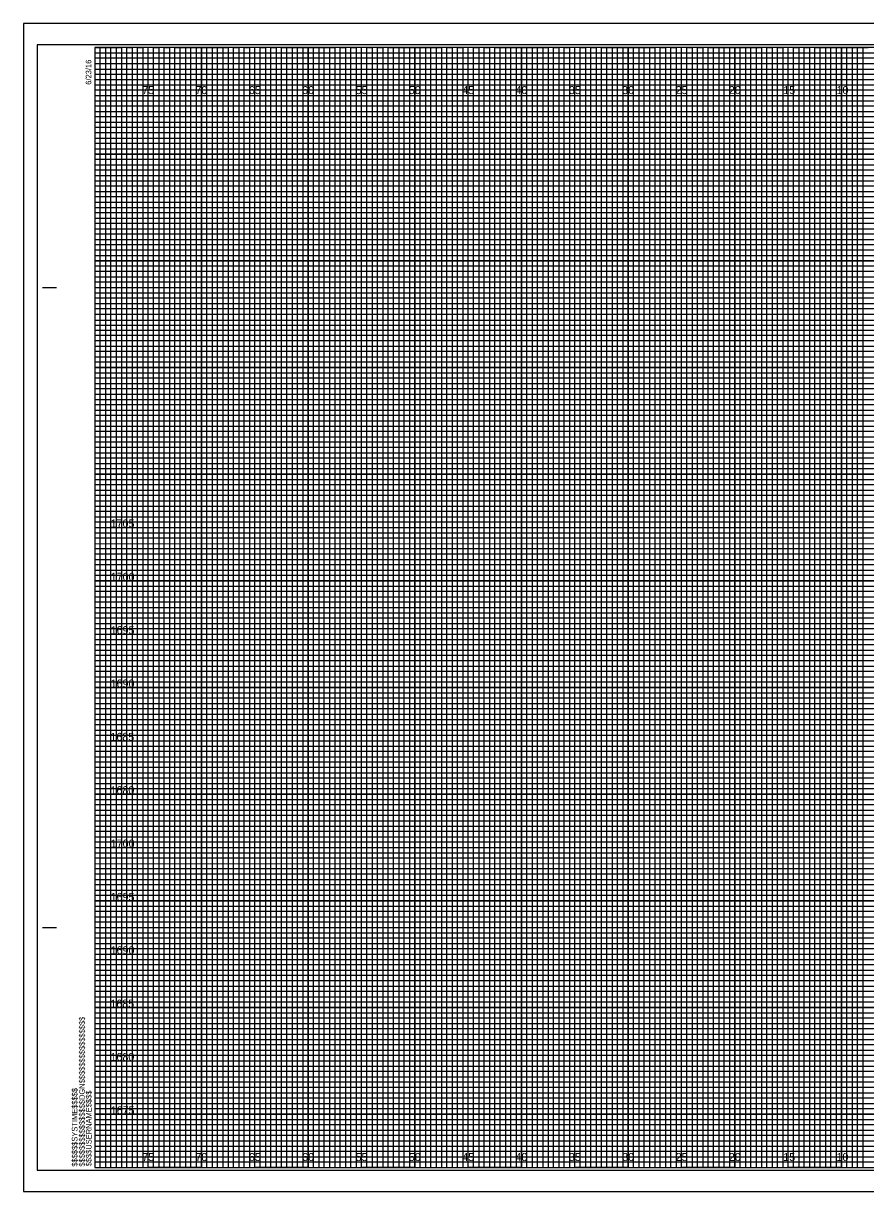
# Model space of a CAD drawing. Extents: x -7 to 162, y -2 to 217.
# Drawn here: x -6.7 to 72.2, y 107.7 to 217.2 of the extents above; entities that cross this region are included whole.
import ezdxf

# ---------------------------------------------------------------- set-up
doc = ezdxf.new("R2010")
doc.units = 0
for name, color, linetype in [('Raster_Level_0', 7, 'Continuous'), ('Scratch_Level_3', 7, 'Continuous'), ('Sheet Cross Section CELL', 7, 'Continuous'), ('Sheet Cross Section Grid Major CELL', 7, 'Continuous'), ('Sheet Cross Section Grid Middle CELL', 7, 'Continuous'), ('Sheet Cross Section Grid Minor 1 CELL', 7, 'Continuous'), ('Sheet Cross Section Grid Minor 2 CELL', 7, 'Continuous'), ('Sheet Cutting Line CELL', 7, 'Continuous'), ('Sheet DOT Grid CELL', 7, 'Continuous'), ('Sheet Plot Border Inside CELL', 7, 'Continuous'), ('Sheet Plot Border Outside CELL', 7, 'Continuous')]:
    doc.layers.add(name, color=color, linetype=linetype)

msp = doc.modelspace()

# ---------------------------------------------------------------- linework, layer by layer
at = {"layer": 'Sheet Cross Section CELL'}
for p, q in [((-4.9, 192.5), (-3.65, 192.5)), ((-4.85, 192.5), (-3.6, 192.5)), ((-4.9, 132.5), (-3.65, 132.5)), ((-4.85, 132.5), (-3.6, 132.5)), ((0, 110), (0, 110)), ((0, 110), (0, 110)), ((0, 110), (0, 110)), ((0, 110), (0, 110)), ((0, 110), (0, 110)), ((0, 110), (0, 110)), ((0, 110), (0, 110))]:
    msp.add_line(p, q, dxfattribs=at)
msp.add_lwpolyline([(160, 215), (0, 215), (0, 110), (160, 110)], close=True, dxfattribs=at)
at = {"layer": 'Sheet Cross Section Grid Major CELL'}
for p, q in [((5, 215), (0, 215)), ((5, 110), (5, 215)), ((15, 215), (10, 215)), ((10, 215), (10, 110)), ((15, 110), (15, 215)), ((25, 215), (20, 215)), ((20, 215), (20, 110)), ((25, 110), (25, 215)), ((35, 215), (30, 215)), ((30, 215), (30, 110)), ((35, 110), (35, 215)), ((45, 215), (40, 215)), ((40, 215), (40, 110)), ((45, 110), (45, 215)), ((55, 215), (50, 215)), ((50, 215), (50, 110)), ((55, 110), (55, 215)), ((65, 215), (60, 215)), ((60, 215), (60, 110)), ((65, 110), (65, 215)), ((75, 215), (70, 215)), ((70, 215), (70, 110)), ((10, 110), (5, 110)), ((20, 110), (15, 110)), ((30, 110), (25, 110)), ((40, 110), (35, 110)), ((50, 110), (45, 110)), ((60, 110), (55, 110)), ((70, 110), (65, 110))]:
    msp.add_line(p, q, dxfattribs=at)
for points in [[(0, 210), (160, 210), (160, 205), (0, 205)], [(0, 200), (160, 200), (160, 195), (0, 195)], [(0, 190), (160, 190), (160, 185), (0, 185)], [(0, 180), (160, 180), (160, 175), (0, 175)], [(0, 170), (160, 170), (160, 165), (0, 165)], [(0, 160), (160, 160), (160, 155), (0, 155)], [(0, 150), (160, 150), (160, 145), (0, 145)], [(0, 140), (160, 140), (160, 135), (0, 135)], [(0, 130), (160, 130), (160, 125), (0, 125)], [(0, 120), (160, 120), (160, 115), (0, 115)]]:
    msp.add_lwpolyline(points, dxfattribs=at)
at = {"layer": 'Sheet Cross Section Grid Middle CELL'}
for points in [[(0, 215), (2.5, 215), (2.5, 110), (7.5, 110), (7.5, 215), (12.5, 215), (12.5, 110), (17.5, 110), (17.5, 215), (22.5, 215), (22.5, 110), (27.5, 110), (27.5, 215), (32.5, 215), (32.5, 110), (37.5, 110), (37.5, 215), (42.5, 215), (42.5, 110), (47.5, 110), (47.5, 215), (52.5, 215), (52.5, 110), (57.5, 110), (57.5, 215), (62.5, 215), (62.5, 110), (67.5, 110), (67.5, 215), (72.5, 215)], [(0, 212.5), (137.5, 212.5)], [(0, 202.5), (160, 202.5), (160, 207.5), (0, 207.5)], [(0, 192.5), (160, 192.5), (160, 197.5), (0, 197.5)], [(0, 182.5), (160, 182.5), (160, 187.5), (0, 187.5)], [(0, 172.5), (160, 172.5), (160, 177.5), (0, 177.5)], [(0, 162.5), (160, 162.5), (160, 167.5), (0, 167.5)], [(0, 152.5), (160, 152.5), (160, 157.5), (0, 157.5)], [(0, 142.5), (160, 142.5), (160, 147.5), (0, 147.5)], [(0, 132.5), (160, 132.5), (160, 137.5), (0, 137.5)], [(0, 122.5), (160, 122.5), (160, 127.5), (0, 127.5)], [(0, 112.5), (160, 112.5), (160, 117.5), (0, 117.5)]]:
    msp.add_lwpolyline(points, dxfattribs=at)
at = {"layer": 'Sheet Cross Section Grid Minor 1 CELL'}
for p, q in [((0, 214.5), (130, 214.5)), ((130, 213.99), (0, 213.99)), ((0, 213.99), (0, 213.5)), ((0, 213.5), (130, 213.5)), ((130, 212.94), (0, 212.94)), ((0, 212.94), (0, 212)), ((0, 212), (160, 212))]:
    msp.add_line(p, q, dxfattribs=at)
for points in [[(0, 211.5), (135, 211.5), (160, 211.5), (160, 211), (0, 211)], [(0, 210.5), (160, 210.5), (160, 209.5), (0, 209.5)], [(0, 209), (160, 209), (160, 208.5), (0, 208.49)], [(0, 208), (160, 208), (160, 207), (0, 207)], [(0, 206.5), (160, 206.5), (160, 206), (0, 206)], [(0, 205.5), (160, 205.5), (160, 204.5), (0, 204.5)], [(0, 204), (160, 204), (160, 203.5), (0, 203.5)], [(0, 203), (160, 203), (160, 202), (0, 202)], [(0, 201.5), (160, 201.5), (160, 201), (0, 201)], [(0, 200.5), (160, 200.5), (160, 199.5), (0, 199.5)], [(0, 199), (160, 199), (160, 198.5), (0, 198.5)], [(0, 198), (160, 198), (160, 196.97), (160, 196.5), (160, 196), (0, 196)], [(0, 197), (160, 197), (160, 196.5), (0, 196.5)], [(0, 195.5), (160, 195.5), (160, 194.5), (0, 194.52)], [(0, 194.52), (160, 194.5), (160, 194), (0, 194)], [(0, 193.5), (160, 193.5), (160, 193), (0, 193)], [(0, 192), (160, 192), (160, 191.5), (0, 191.5)], [(0, 191), (160, 191), (160, 190.5), (0, 190.5)], [(-0.04, 189.44), (160, 189.44), (160, 188.94), (-0.04, 188.94)], [(0, 188.5), (160, 188.5), (160, 188), (0, 188)], [(0, 187), (160, 187), (160, 186.5), (0, 186.5)], [(0, 186), (160, 186), (160, 185.5), (0, 185.5)], [(0, 184.5), (160, 184.5), (160, 184), (0, 184)], [(0, 183.5), (160, 183.5), (160, 183), (0, 183)], [(0, 182), (160, 182), (160, 181.5), (0, 181.5)], [(0, 181), (160, 181), (160, 180.5), (0, 180.5)], [(0, 179.5), (160, 179.5), (160, 178.99), (0, 179)], [(0, 178.5), (160, 178.5), (160, 178), (0, 178)], [(0, 177), (160, 177), (160, 176.5), (0, 176.5)], [(0, 176), (160, 176), (160, 175.5), (0, 175.5)], [(0, 174.5), (160, 174.5), (160, 174), (0, 174)], [(0, 173.5), (160, 173.5), (160, 173), (0, 173)], [(0, 172), (160, 172), (160, 171.5), (0, 171.5)], [(0, 171), (160, 171), (160, 170.5), (0, 170.5)], [(0, 169.5), (160, 169.5), (160, 169), (0, 169)], [(0, 168.5), (160.03, 168.46), (160, 168), (0, 168)], [(0, 167), (160, 167), (160, 166.5), (0, 166.5)], [(0, 166), (160, 166), (160, 165.5), (0, 165.5)], [(0, 164.5), (160, 164.5), (160, 164), (0, 164)], [(0, 163.5), (160, 163.5), (160, 163), (0, 163)], [(0, 162), (160, 162), (160, 161.5), (0, 161.5)], [(0, 161), (160, 161), (160, 160.5), (0, 160.5)], [(0, 159.5), (160, 159.5), (160, 159), (0, 159)], [(0, 158.5), (160, 158.5), (160, 158), (0, 158)], [(0, 157), (160, 157), (160, 156.5), (0, 156.5)], [(0, 156), (160, 156), (160, 155.5), (0, 155.5)], [(0, 154.5), (160, 154.5), (160, 154), (0, 154)], [(0, 153.5), (160, 153.5), (160, 153), (0, 153)], [(0, 152), (160, 152), (160, 151.5), (0, 151.5)], [(0, 151), (160, 151), (160, 150.5), (0, 150.5)], [(0, 149.5), (160, 149.5), (160, 148.99), (0, 149)], [(0, 148.5), (160, 148.5), (160, 148), (0, 148)], [(0, 147), (160, 147), (160, 146.5), (0, 146.5)], [(0, 146), (160, 146), (160, 145.5), (0, 145.5)], [(0, 144.5), (160, 144.5), (160, 144), (0, 144)], [(0, 143.5), (160, 143.5), (160, 143), (0, 143)], [(0, 142), (160, 142), (160, 141.5), (0, 141.5)], [(0, 141), (160, 141), (160, 140.5), (0, 140.5)], [(0, 139.5), (160, 139.5), (160, 139), (0, 139)], [(0, 138.5), (160.03, 138.46), (160, 138), (0, 138)], [(0, 137), (160, 137), (160, 136.5), (0, 136.5)], [(0, 136), (160, 136), (160, 135.5), (0, 135.5)], [(0, 134.5), (160, 134.5), (160, 134), (0, 134)], [(0, 133.5), (160, 133.5), (160, 133), (0, 133)], [(0, 132), (160, 132), (160, 131.5), (0, 131.5)], [(0, 131), (160, 131), (160, 130.5), (0, 130.5)], [(0, 129.5), (160, 129.5), (160, 129), (0, 129)], [(0, 128.5), (160, 128.5), (160, 128), (0, 128)], [(0, 127), (160, 127), (160, 126.5), (0, 126.5)], [(0, 126), (160, 126), (160, 125.5), (0, 125.5)], [(0, 124.5), (160, 124.5), (160, 124), (0, 124)], [(0, 123.5), (160, 123.5), (160, 123), (0, 123)], [(0, 122), (160, 122), (160, 121.5), (0, 121.5)], [(0, 121), (160, 121), (160, 120.5), (0, 120.5)], [(0, 119.5), (160, 119.5), (160, 119), (0, 119)], [(0, 118.5), (160, 118.5), (160, 118), (0, 118)], [(0, 117), (160, 117), (160, 116.5), (0, 116.5)], [(0, 116), (160, 116), (160, 115.5), (0, 115.5)], [(0, 114.5), (160, 114.5), (160, 114), (0, 114)], [(0, 113.5), (160, 113.5), (160, 113), (0, 113)], [(0, 112), (160, 112), (160, 111.5), (0, 111.5)], [(0, 111), (160, 111), (160, 110.5), (0, 110.5)]]:
    msp.add_lwpolyline(points, dxfattribs=at)
at = {"layer": 'Sheet Cross Section Grid Minor 2 CELL'}
for points in [[(0, 110), (0.5, 110), (0.5, 215), (1, 215), (1, 110)], [(1, 110), (1.5, 110), (1.5, 215), (2, 215), (2, 110)], [(2.5, 110), (3, 110), (3, 215), (3.5, 215), (3.5, 110)], [(3.5, 110), (4, 110), (4, 215), (4.5, 215), (4.5, 110)], [(5, 110), (5.5, 110), (5.5, 215), (6, 215), (6, 110)], [(6, 110), (6.5, 110), (6.5, 215), (7, 215), (7, 110)], [(7.5, 110), (8, 110), (8, 215), (8.5, 215), (8.5, 110)], [(8.5, 110), (9, 110), (9, 215), (9.5, 215), (9.5, 110)], [(10, 110), (10.5, 110), (10.5, 215), (11, 215), (11, 110)], [(11, 110), (11.5, 110), (11.5, 215), (12, 215), (12, 110)], [(12.5, 110), (13, 110), (13, 215), (13.5, 215), (13.5, 110)], [(13.5, 110), (14, 110), (14, 215), (14.5, 215), (14.5, 110)], [(15, 110), (15.5, 110), (15.5, 215), (16, 215), (16, 110)], [(16, 110), (16.5, 110), (16.5, 215), (17, 215), (17, 110)], [(17.5, 110), (18, 110), (18, 215), (18.5, 215), (18.5, 110)], [(18.5, 110), (19, 110), (19, 215), (19.5, 215), (19.5, 110)], [(20, 110), (20.5, 110), (20.5, 215), (21, 215), (21, 110)], [(21, 110), (21.5, 110), (21.5, 215), (22, 215), (22, 110)], [(22.5, 110), (23, 110), (23, 215), (23.5, 215), (23.5, 110)], [(23.5, 110), (24, 110), (24, 215), (24.5, 215), (24.5, 110)], [(25, 110), (25.5, 110), (25.5, 215), (26, 215), (26, 110)], [(26, 110), (26.5, 110), (26.5, 215), (27, 215), (27, 110)], [(27.5, 110), (28, 110), (28, 215), (28.5, 215), (28.5, 110)], [(28.5, 110), (29, 110), (29, 215), (29.5, 215), (29.5, 110)], [(30, 110), (30.5, 110), (30.5, 215), (31, 215), (31, 110)], [(31, 110), (31.5, 110), (31.5, 215), (32, 215), (32, 110)], [(32.5, 110), (33, 110), (33, 215), (33.5, 215), (33.5, 110)], [(33.5, 110), (34, 110), (34, 215), (34.5, 215), (34.5, 110)], [(35, 110), (35.5, 110), (35.5, 215), (36, 215), (36, 110)], [(36, 110), (36.5, 110), (36.5, 215), (37, 215), (37, 110)], [(37.5, 110), (38, 110), (38, 215), (38.5, 215), (38.5, 110)], [(38.5, 110), (39, 110), (39, 215), (39.5, 215), (39.5, 110)], [(40, 110), (40.5, 110), (40.5, 215), (41, 215), (41, 110)], [(41, 110), (41.5, 110), (41.5, 215), (42, 215), (42, 110)], [(42.5, 110), (43, 110), (43, 215), (43.5, 215), (43.5, 110)], [(43.5, 110), (44, 110), (44, 215), (44.5, 215), (44.5, 110)], [(45, 110), (45.5, 110), (45.5, 215), (46, 215), (46, 110)], [(46, 110), (46.5, 110), (46.5, 215), (47, 215), (47, 110)], [(47.5, 110), (48, 110), (48, 215), (48.5, 215), (48.5, 110)], [(48.5, 110), (49, 110), (49, 215), (49.5, 215), (49.5, 110)], [(50, 110), (50.5, 110), (50.5, 215), (51, 215), (51, 110)], [(51, 110), (51.5, 110), (51.5, 215), (52, 215), (52, 110)], [(52.5, 110), (53, 110), (53, 215), (53.5, 215), (53.5, 110)], [(53.5, 110), (54, 110), (54, 215), (54.5, 215), (54.5, 110)], [(55, 110), (55.5, 110), (55.5, 215), (56, 215), (56, 110)], [(56, 110), (56.5, 110), (56.5, 215), (57, 215), (57, 110)], [(57.5, 110), (58, 110), (58, 215), (58.5, 215), (58.5, 110)], [(58.5, 110), (59, 110), (59, 215), (59.5, 215), (59.5, 110)], [(60, 110), (60.5, 110), (60.5, 215), (61, 215), (61, 110)], [(61, 110), (61.5, 110), (61.5, 215), (62, 215), (62, 110)], [(62.5, 110), (63, 110), (63, 215), (63.5, 215), (63.5, 110)], [(63.5, 110), (64, 110), (64, 215), (64.5, 215), (64.5, 110)], [(65, 110), (65.5, 110), (65.5, 215), (66, 215), (66, 110)], [(66, 110), (66.5, 110), (66.5, 215), (67, 215), (67, 110)], [(67.5, 110), (68, 110), (68, 215), (68.5, 215), (68.5, 110)], [(68.5, 110), (69, 110), (69, 215), (69.5, 215), (69.5, 110)], [(70, 110), (70.5, 110), (70.5, 215), (71, 215), (71, 110)], [(71, 110), (71.5, 110), (71.5, 215), (72, 215), (72, 110)]]:
    msp.add_lwpolyline(points, dxfattribs=at)
at = {"layer": 'Sheet Cutting Line CELL'}
for p, q in [((161.65, 217.25), (-6.7, 217.25)), ((-6.7, 217.25), (-6.7, 107.75)), ((-6.7, 107.75), (161.65, 107.75))]:
    msp.add_line(p, q, dxfattribs=at)
at = {"layer": 'Sheet DOT Grid CELL'}
for p, q in [((5, 110), (5, 215)), ((10, 110), (10, 215)), ((15, 110), (15, 215)), ((20, 110), (20, 215)), ((25, 110), (25, 215)), ((30, 110), (30, 215)), ((35, 110), (35, 215)), ((40, 110), (40, 215)), ((45, 110), (45, 215)), ((50, 110), (50, 215)), ((55, 110), (55, 215)), ((60, 110), (60, 215)), ((65, 110), (65, 215)), ((70, 110), (70, 215)), ((0, 210), (160, 210)), ((0, 205), (160, 205)), ((0, 200), (160, 200)), ((0, 195), (160, 195)), ((0, 190), (160, 190)), ((0, 185), (160, 185)), ((0, 180), (160, 180)), ((0, 175), (160, 175)), ((0, 170), (160, 170)), ((0, 165), (160, 165)), ((0, 160), (160, 160)), ((0, 155), (160, 155)), ((0, 150), (160, 150)), ((0, 145), (160, 145)), ((0, 140), (160, 140)), ((0, 135), (160, 135)), ((0, 130), (160, 130)), ((0, 125), (160, 125)), ((0, 120), (160, 120)), ((0, 115), (160, 115))]:
    msp.add_line(p, q, dxfattribs=at)
at = {"layer": 'Sheet Plot Border Inside CELL'}
msp.add_lwpolyline([(-5.4, 109.75), (161.2, 109.75), (161.2, 215.25), (-5.4, 215.25)], close=True, dxfattribs=at)
at = {"layer": 'Sheet Plot Border Outside CELL'}
msp.add_lwpolyline([(-6.7, 107.75), (161.65, 107.75), (161.65, 217.25), (-6.7, 217.25)], close=True, dxfattribs=at)

# ---------------------------------------------------------------- texts
at = {"layer": 'Raster_Level_0'}
for s, p in [('75', (4.44, 210.62)), ('70', (9.43, 210.62)), ('65', (14.44, 210.62)), ('60', (19.43, 210.62)), ('55', (24.44, 210.62)), ('50', (29.43, 210.62)), ('45', (34.44, 210.62)), ('40', (39.43, 210.62)), ('35', (44.44, 210.62)), ('30', (49.43, 210.62)), ('25', (54.44, 210.62)), ('20', (59.43, 210.62)), ('15', (64.53, 210.62)), ('10', (69.52, 210.62)), ('75', (4.44, 110.62)), ('70', (9.43, 110.62)), ('65', (14.44, 110.62)), ('60', (19.43, 110.62)), ('55', (24.44, 110.62)), ('50', (29.43, 110.62)), ('45', (34.44, 110.62)), ('40', (39.43, 110.62)), ('35', (44.44, 110.62)), ('30', (49.43, 110.62)), ('25', (54.44, 110.62)), ('20', (59.43, 110.62)), ('15', (64.53, 110.62)), ('10', (69.52, 110.62))]:
    msp.add_text(s, height=0.75, dxfattribs=at).set_placement(p)
at = {"layer": 'Scratch_Level_3'}
for s, p in [('1705', (1.48, 170)), ('1700', (1.49, 165)), ('1695', (1.48, 160)), ('1690', (1.48, 155)), ('1685', (1.46, 150)), ('1680', (1.47, 145)), ('1700', (1.49, 140)), ('1695', (1.48, 135)), ('1690', (1.48, 130)), ('1685', (1.46, 125)), ('1680', (1.47, 120)), ('1675', (1.49, 115))]:
    msp.add_text(s, height=0.75, dxfattribs=at).set_placement(p)
at = {"layer": 'Sheet Cross Section CELL'}
for s, p in [('6/23/16', (-0.33, 211.5)), ('$$$$$$$$$$$$$$$$DGN$$$$$$$$$$$$$$$$', (-0.94, 110.09)), ('$$$$$$SYSTIME$$$$$', (-1.63, 110.09)), ('$$$$USERNAME$$$$', (-0.31, 110.12))]:
    msp.add_text(s, height=0.525, rotation=90, dxfattribs=at).set_placement(p)

doc.saveas('drawing.dxf')
